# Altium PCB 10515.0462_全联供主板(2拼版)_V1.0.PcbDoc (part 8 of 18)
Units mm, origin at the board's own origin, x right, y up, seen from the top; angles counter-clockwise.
Board outline 282 x 198 mm, 2 copper layers (Top Layer, Bottom Layer); 716 components, 0 nets, 2364 pads, 1800 vias.
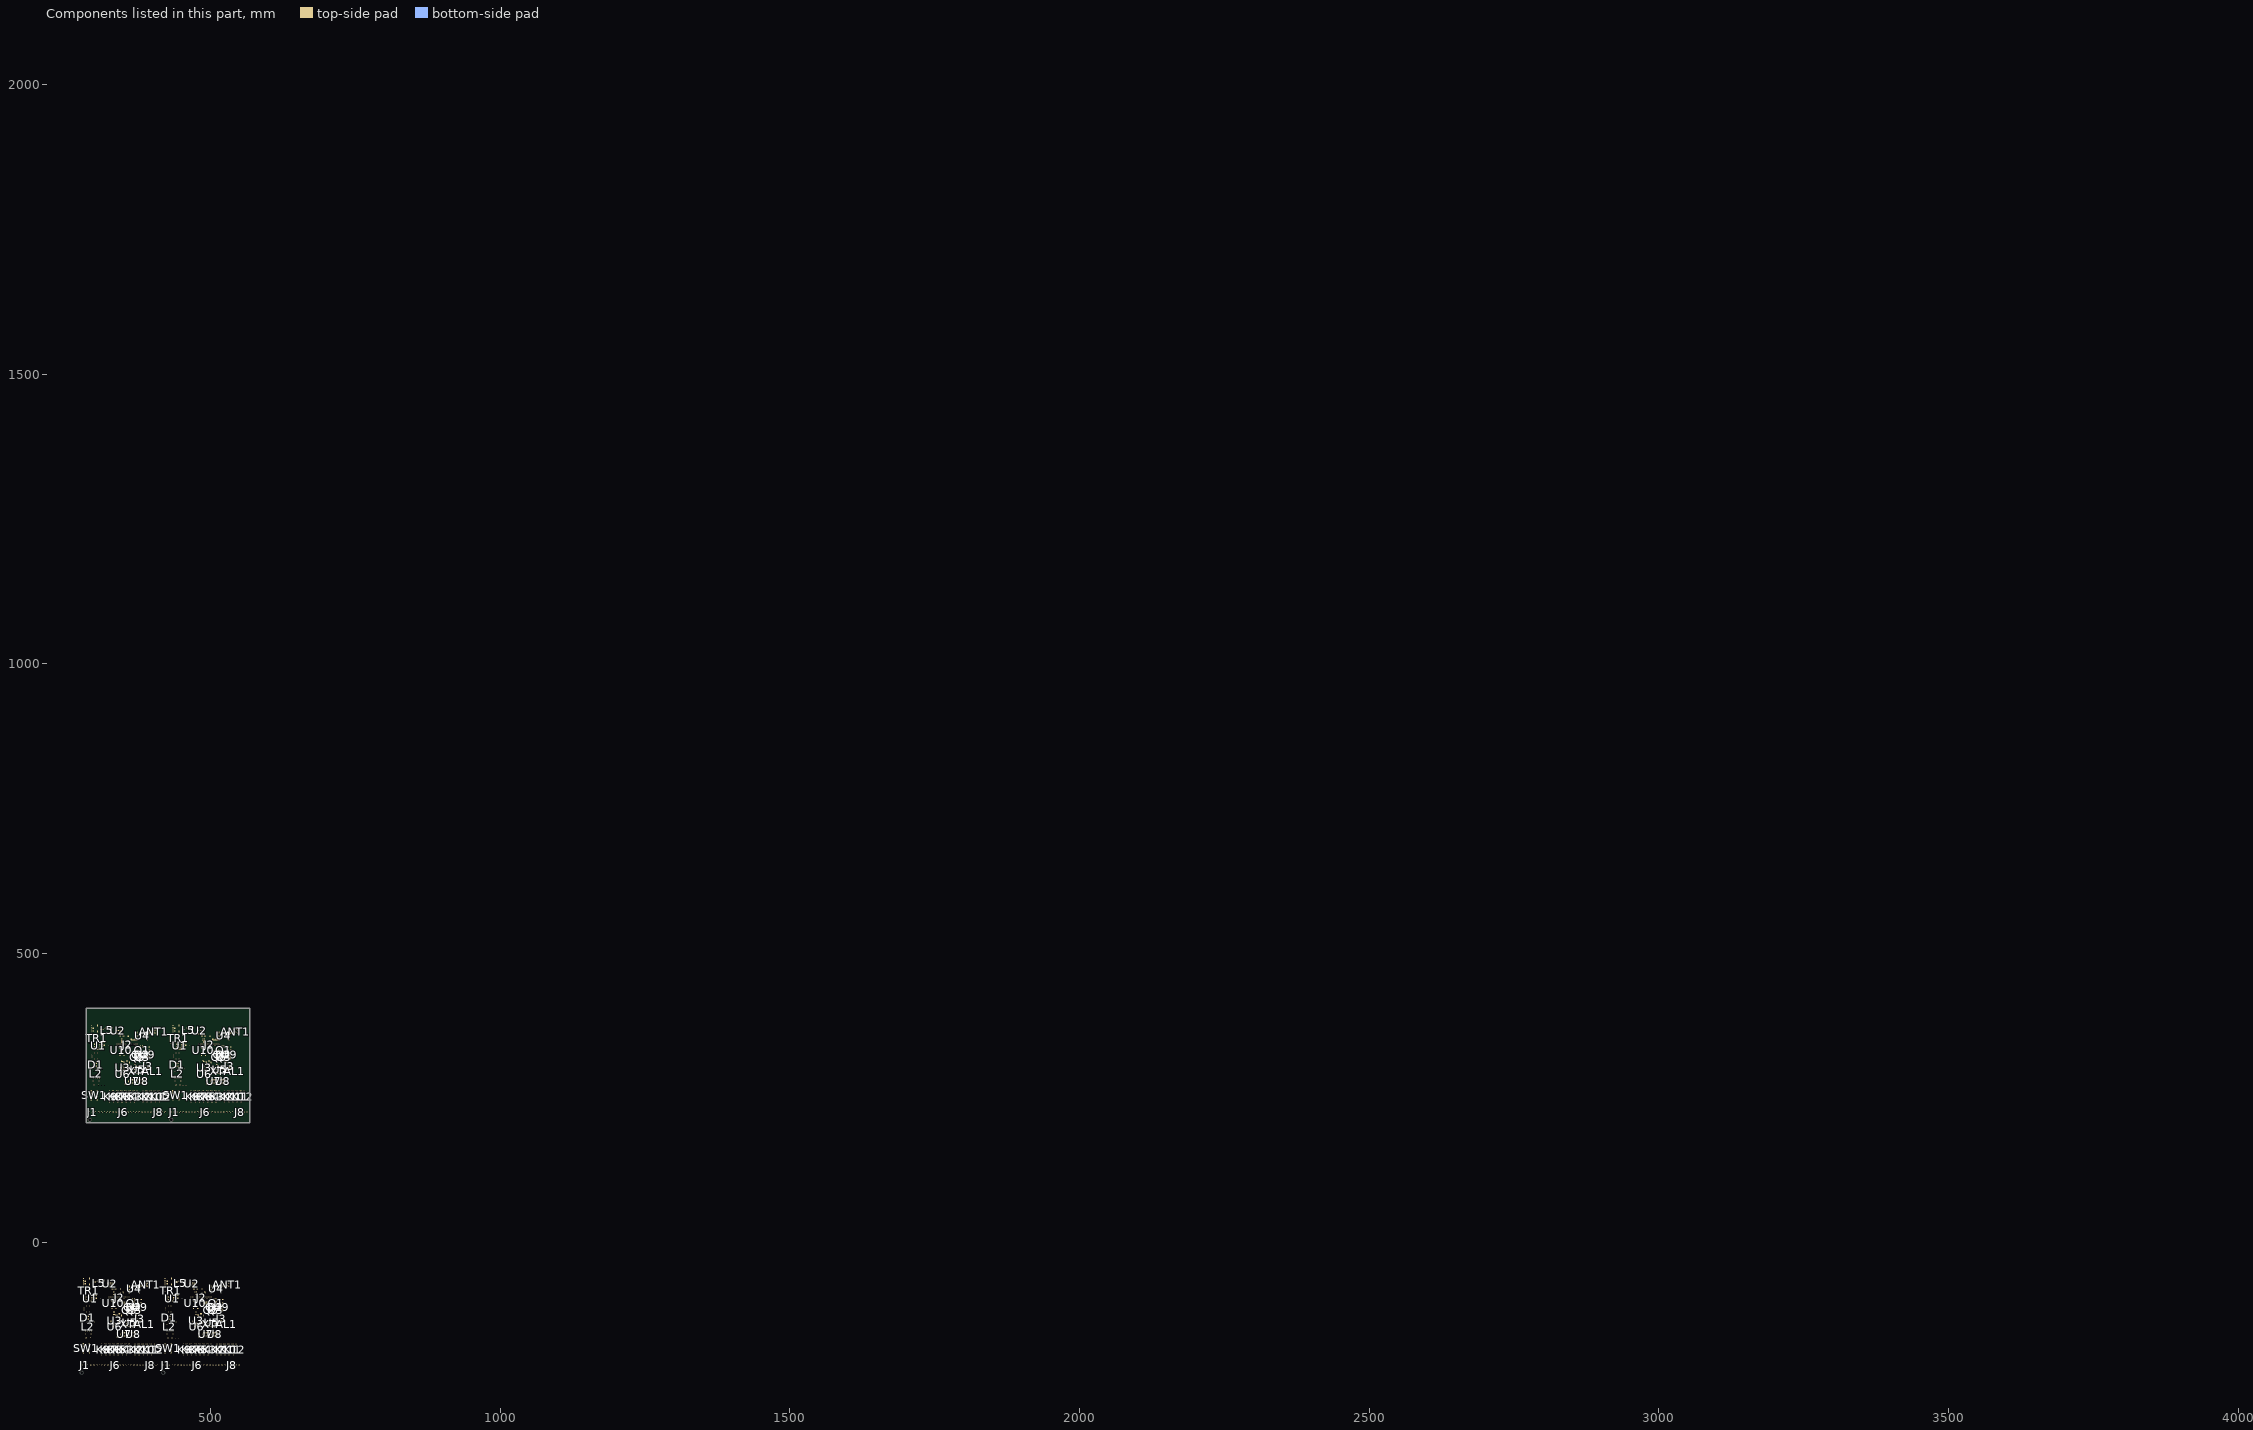
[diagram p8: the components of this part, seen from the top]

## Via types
v1: diameter 0.7, hole 0.4, Top Layer to Bottom Layer, tented both sides, 1800 vias

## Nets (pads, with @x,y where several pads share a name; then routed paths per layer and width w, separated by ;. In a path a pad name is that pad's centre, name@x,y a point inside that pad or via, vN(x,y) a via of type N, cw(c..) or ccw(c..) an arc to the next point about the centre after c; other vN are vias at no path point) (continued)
copper on no net: (continued)
  Top Layer w0.45: 524.977,-73.768 cw(c523.631,-72.858) v1@523.631,-74.482 ; 525.138,-173.772 cw(c526.042,-172.764) 524.687,-172.764 ; 525.228,320.25 cw(c524.918,319.941) 525.356,319.941 cw(c525.794,319.941) 525.484,320.25 ; 525.228,326.817 ccw(c524.918,327.127) 525.356,327.127 ccw(c525.794,327.127) 525.484,326.817 ; 525.349,-74.944 ccw(c524.479,-75.533) 524.479,-74.482 ccw(c524.479,-73.431) 525.349,-74.02 ; 525.917,-74.482 v1@523.631,-74.482 ; 525.991,297.303 527.608,297.303 527.999,297.693 527.999,299.132 528.448,299.582 ; 526.119,297.174 cw(c526.429,296.865) 526.429,297.303 cw(c526.429,297.741) 526.119,297.431 ; 526.512,297.303 ccw(c526.512,299.055) 527.751,297.816 ; 527.297,338.398 ccw(c527.297,340.869) 529.043,339.122 ; 527.742,-72.773 ccw(c525.736,-74.779) 525.736,-71.942 ccw(c525.736,-69.105) 527.742,-71.111 ; 527.751,294.821 cw(c526.786,293.855) 528.151,293.855 ; 527.751,298.066 ccw(c527.154,298.663) 527.999,298.663 ccw(c528.844,298.663) 528.246,298.066 ; 527.999,295.193 528.151,295.041 528.151,293.325 528.151,292.539 528.337,292.352 531.071,292.352 531.452,292.733 531.452,296.963 v1(531.418,296.996) 530.721,297.693 ; 527.999,298.151 cw(c529.842,298.151) 528.539,299.454 ; 527.999,298.973 cw(c528.427,298.973) 528.415,299.401 ; 527.999,299.237 cw(c528.755,299.237) 528.22,299.772 ; 528.023,293.197 cw(c527.713,292.887) 528.151,292.887 cw(c528.589,292.887) 528.279,293.197 ; 528.023,293.454 ccw(c527.713,293.763) 528.151,293.763 ccw(c528.589,293.763) 528.279,293.454 ; 528.06,-72.455 ccw(c526.822,-73.692) 526.822,-71.942 ccw(c526.822,-70.192) 528.06,-71.429 ; 528.074,299.207 ccw(c527.699,299.582) 528.229,299.582 ; v1(528.226,326.19) 529.082,326.19 ; 528.383,338.398 ccw(c528.383,339.782) 529.362,338.804 ; 528.523,338.398 cw(c528.523,337.663) 529.043,338.183 ; 528.751,303.075 ccw(c528.441,303.385) 528.879,303.385 ccw(c529.317,303.385) 529.008,303.075 ; 528.879,302.947 528.879,303.602 529.259,303.981 531.291,303.981 532.144,304.834 532.144,305.31 ; 528.954,326.061 ccw(c528.644,325.752) 528.644,326.19 ccw(c528.644,326.628) 528.954,326.318 ; 529.082,326.317 529.437,325.961 v1(533.513,325.961) v1@533.64,325.961 ; 529.21,326.28 ccw(c529.98,327.049) 529.98,325.961 ; 529.424,332.983 cw(c528.291,331.849) 529.894,331.849 cw(c531.497,331.849) 530.363,332.983 ; 529.443,333.94 ccw(c528.493,334.969) v1(529.894,334.969) ccw(c531.295,334.969) 530.344,333.94 ; 529.674,293.454 ccw(c529.364,293.763) 529.802,293.763 ccw(c530.24,293.763) 529.93,293.454 ; 529.751,298.066 ccw(c529.154,298.663) 529.999,298.663 ccw(c530.844,298.663) 530.246,298.066 ; 529.802,293.325 529.802,294.997 529.999,295.193 ; 529.802,293.749 cw(c531.318,293.749) 530.246,294.821 ; 529.894,331.285 529.894,333.452 v1(529.894,334.969) ; 529.894,331.992 ccw(c531.075,331.992) 530.24,331.157 ; 529.933,297.644 cw(c530.351,297.161) 530.802,297.612 ; 529.958,319.548 ccw(c528.412,321.095) 530.598,321.095 ; 529.989,297.668 cw(c530.133,296.21) 531.169,297.246 ; 529.999,298.993 cw(c530.65,298.993) 530.19,299.454 ; 530.086,319.382 530.598,319.894 530.598,322.246 ; 530.086,319.602 ccw(c530.086,320.132) 530.461,319.757 ; 530.099,299.582 529.999,299.481 529.999,297.693 530.721,297.693 ; 530.227,297.303 cw(c530.668,296.793) 531.145,297.27 ; 530.273,297.476 cw(c530.721,297.123) 530.721,297.693 ; 530.273,297.91 ccw(c530.721,298.264) 530.721,297.693 ; 530.276,319.23 ccw(c529.498,320.008) 530.598,320.008 ; 530.402,301.431 ccw(c530.092,301.741) 530.53,301.741 ccw(c530.968,301.741) 530.659,301.431 ; 530.402,302.819 cw(c530.092,302.509) 530.53,302.509 cw(c530.968,302.509) 530.659,302.819 ; 530.53,302.947 530.53,301.341 532.308,301.341 532.312,301.338 ; 530.598,325.961 530.598,328.342 ; 530.659,301.175 cw(c531.06,300.773) 531.06,301.341 ; 530.744,338.183 cw(c531.265,337.663) 531.265,338.398 ; 530.779,262.851 ccw(c530.1,263.712) 531.197,263.712 ; 530.905,338.861 ccw(c531.545,339.072) 531.545,338.398 ; 531.197,261.97 531.197,263.712 ; 531.322,-173.798 ccw(c530.169,-172.645) 531.799,-172.645 ccw(c533.429,-172.645) 532.276,-173.798 ; v1@531.33,296.908 cw(c531.034,296.613) 531.452,296.613 ; 531.506,319.548 ccw(c530.632,320.423) v1@531.868,320.423 ; 531.592,304.283 ccw(c531.12,304.755) 531.676,305.125 ; 531.615,262.851 cw(c532.294,263.712) 531.197,263.712 ; 531.634,319.382 531.868,319.616 v1(531.868,320.491) 531.868,322.246 ; 531.672,331.157 ccw(c531.363,331.467) 531.801,331.467 ccw(c532.239,331.467) 531.929,331.157 ; 531.709,301.341 cw(c531.709,300.773) 532.111,301.175 ; 531.71,330.901 cw(c531.329,330.52) 531.868,330.52 ; 531.801,331.029 531.801,338.143 531.545,338.398 ; 531.868,328.342 531.868,330.961 ; v1@531.937,320.594 533.138,320.594 533.138,322.246 ; v1@531.957,320.403 cw(c532.419,319.941) 532.419,320.594 ; 532.047,302.632 cw(c531.406,301.992) 532.312,301.992 cw(c533.217,301.992) 532.577,302.632 ; 532.187,301.431 ccw(c531.886,301.732) 532.312,301.732 ; 532.277,301.303 532.312,301.338 ; 532.312,301.75 ccw(c532.762,301.75) 532.444,301.431 ; 532.312,302.838 532.312,301.338 ; 533.005,336.938 ccw(c531.386,338.558) 533.675,338.631 ; 533.183,319.382 534.731,319.382 ; 533.196,331.157 ccw(c532.887,331.467) 533.325,331.467 ccw(c533.763,331.467) 533.453,331.157 ; 533.311,319.254 cw(c533.621,318.944) 533.621,319.382 cw(c533.621,319.82) 533.311,319.51 ; 533.325,331.029 533.325,331.793 532.815,332.302 532.815,336.747 534.72,338.652 ; 533.74,337.673 ccw(c532.809,338.603) 534.125,338.646 ; 533.856,337.788 cw(c534.339,337.305) 534.339,337.988 ; 533.923,339.17 ccw(c533.012,340.303) 534.466,340.303 ; 533.928,301.303 534.318,301.303 535.912,302.897 535.912,305.078 536.144,305.31 ; 533.966,301.484 ccw(c533.966,302.771) 534.876,301.861 ; 534.303,333.969 ccw(c533.597,334.842) v1(534.72,334.842) ccw(c535.843,334.842) 535.137,333.969 ; 534.408,319.44 534.408,322.246 ; 534.408,320.638 ccw(c535.949,320.638) 534.86,319.548 ; 534.408,324.539 v1(534.408,326.841) ; 534.466,339.949 ccw(c535.635,339.949) 534.808,339.122 ; 534.603,319.254 ccw(c534.293,318.944) 534.293,319.382 ccw(c534.293,319.82) 534.603,319.51 ; 534.72,333.452 v1(534.72,334.842) ; 534.885,330.901 cw(c533.445,329.461) 535.482,329.461 ; 534.93,301.915 ccw(c533.949,302.897) 535.337,302.897 ; 534.976,331.029 535.482,330.523 535.482,326.206 v1(535.228,325.952) ; 535.003,330.848 cw(c534.972,330.339) 535.482,330.339 ; v1@535.14,326.041 ccw(c534.313,326.867) 535.482,326.867 ; 535.195,331.029 ccw(c535.725,331.029) 535.35,330.654 ; 535.204,331.219 cw(c534.532,330.547) 535.482,330.547 ; 535.647,303.162 ccw(c535.006,303.802) 535.912,303.802 ccw(c536.817,303.802) 536.177,303.162 ; 535.746,305.039 cw(c535.346,304.639) 535.912,304.639 ; 535.912,303.519 cw(c538.062,303.519) 536.541,305.039 ; 535.912,304.606 cw(c536.975,304.606) 536.223,305.358 ; 536.042,364.82 536.208,364.654 542.201,364.654 ; 536.311,364.538 cw(c536.59,364.259) 536.59,364.654 ; 536.311,364.795 ccw(c536.651,365.135) 536.651,364.654 ; 537.865,262.823 ccw(c536.961,263.832) 538.316,263.832 ; 538.316,261.97 538.316,263.832 ; 538.561,-173.798 ccw(c537.408,-172.645) 539.038,-172.645 ccw(c540.668,-172.645) 539.515,-173.798 ; 538.605,361.399 ccw(c537.26,360.49) v1@537.26,362.114 ; 538.605,362.828 cw(c537.26,363.738) v1@537.26,362.114 ; 538.766,262.823 cw(c539.671,263.832) 538.316,263.832 ; 538.978,361.651 ccw(c538.108,361.063) 538.108,362.114 ccw(c538.108,363.164) 538.978,362.576 ; 539.546,362.114 v1@537.26,362.114 ; 541.371,363.823 ccw(c539.365,361.817) 539.365,364.654 ccw(c539.365,367.49) 541.371,365.484 ; 541.689,364.141 ccw(c540.451,362.903) 540.451,364.654 ccw(c540.451,366.404) 541.689,365.166 ; 544.95,262.798 ccw(c543.798,263.95) 545.428,263.95 ccw(c547.057,263.95) 545.905,262.798 ; 552.189,262.798 ccw(c551.037,263.95) 552.667,263.95 ccw(c554.296,263.95) 553.144,262.798 ; 321.544,-71.781 321.925,-71.781 ; 321.544,-71.781 321.544,-71.219 321.598,-71.273 322.433,-71.273 ; 321.925,-71.781 322.433,-71.273 ; 322.433,-71.273 cw(c322.433,-70.843) 322.012,-70.93 ccw(c322.433,-70.843) 322.433,-71.273 ; 322.433,-71.273 v1@322.814,-71.273 ; 335.173,364.814 335.554,364.814 ; 335.173,364.814 335.173,365.377 335.227,365.322 336.062,365.322 ; 335.554,364.814 336.062,365.322 ; 336.062,365.322 cw(c336.062,365.753) 335.64,365.665 ccw(c336.062,365.753) 336.062,365.322 ; 336.062,365.322 v1@336.443,365.322 ; 345.683,-158.635 346.309,-158.635 ; 345.86,-156.984 346.343,-156.501 346.343,-156.236 ; 345.86,-156.984 344.488,-156.984 344.756,-157.252 359.009,-157.252 ; 345.86,-156.984 359.982,-156.984 ; 346.309,-158.635 359.982,-158.635 360.406,-158.635 ; 355.233,-174.116 354.597,-174.752 355.233,-174.116 ; 355.233,-174.116 355.233,-171.222 ; 359.009,-157.252 361.086,-157.252 361.71,-156.628 ; 359.009,-157.252 359.714,-157.252 359.982,-156.984 ; 359.311,277.96 359.938,277.96 ; 359.489,279.611 359.972,280.094 359.972,280.359 ; 359.489,279.611 358.117,279.611 358.385,279.343 372.638,279.343 ; 359.489,279.611 373.611,279.611 ; 359.938,277.96 373.611,277.96 374.035,277.96 ; 359.982,-156.984 360.787,-156.984 ; 360.113,-158.76 cw(c360.406,-159.04) 360.406,-158.635 ; 360.113,-158.76 cw(c360.406,-159.04) 360.406,-158.635 ; 360.113,-158.76 cw(c360.406,-159.04) 360.406,-158.635 ; 360.113,-158.51 ccw(c360.406,-158.23) 360.406,-158.635 ; 360.113,-158.51 ccw(c360.406,-158.23) 360.406,-158.635 ; 360.113,-158.51 ccw(c360.406,-158.23) 360.406,-158.635 ; 360.42,-158.635 ccw(c360.42,-159.073) 360.11,-158.763 cw(c360.42,-159.073) 360.42,-158.635 ; 360.42,-158.635 cw(c360.42,-158.197) 360.11,-158.507 ccw(c360.42,-158.197) 360.42,-158.635 ; 360.787,-156.984 361.354,-156.984 361.71,-156.628 ; 368.862,262.479 368.226,261.843 368.862,262.479 ; 368.862,262.479 368.862,265.373 ; 372.638,279.343 374.715,279.343 375.339,279.967 ; 372.638,279.343 373.343,279.343 373.611,279.611 ; 373.611,279.611 374.416,279.611 ; 373.742,277.835 cw(c374.035,277.555) 374.035,277.96 ; 373.742,277.835 cw(c374.035,277.555) 374.035,277.96 ; 373.742,277.835 cw(c374.035,277.555) 374.035,277.96 ; 373.742,278.086 ccw(c374.035,278.365) 374.035,277.96 ; 373.742,278.086 ccw(c374.035,278.365) 374.035,277.96 ; 373.742,278.086 ccw(c374.035,278.365) 374.035,277.96 ; 374.049,277.96 ccw(c374.049,277.523) 373.739,277.832 cw(c374.049,277.523) 374.049,277.96 ; 374.049,277.96 cw(c374.049,278.398) 373.739,278.089 ccw(c374.049,278.398) 374.049,277.96 ; 374.416,279.611 374.983,279.611 375.339,279.967 ; 462.544,-71.781 462.925,-71.781 ; 462.544,-71.781 462.544,-71.219 462.598,-71.273 463.433,-71.273 ; 462.925,-71.781 463.433,-71.273 ; 463.433,-71.273 cw(c463.433,-70.843) 463.012,-70.93 ccw(c463.433,-70.843) 463.433,-71.273 ; 463.433,-71.273 v1@463.814,-71.273 ; 476.173,364.814 476.554,364.814 ; 476.173,364.814 476.173,365.377 476.227,365.322 477.062,365.322 ; 476.554,364.814 477.062,365.322 ; 477.062,365.322 cw(c477.062,365.753) 476.64,365.665 ccw(c477.062,365.753) 477.062,365.322 ; 477.062,365.322 v1@477.443,365.322 ; 486.683,-158.635 487.309,-158.635 ; 486.86,-156.984 487.343,-156.501 487.343,-156.236 ; 486.86,-156.984 485.488,-156.984 485.756,-157.252 500.009,-157.252 ; 486.86,-156.984 500.982,-156.984 ; 487.309,-158.635 500.982,-158.635 501.406,-158.635 ; 496.233,-174.116 495.597,-174.752 496.233,-174.116 ; 496.233,-174.116 496.233,-171.222 ; 500.009,-157.252 502.086,-157.252 502.71,-156.628 ; 500.009,-157.252 500.714,-157.252 500.982,-156.984 ; 500.311,277.96 500.938,277.96 ; 500.489,279.611 500.972,280.094 500.972,280.359 ; 500.489,279.611 499.117,279.611 499.385,279.343 513.638,279.343 ; 500.489,279.611 514.611,279.611 ; 500.938,277.96 514.611,277.96 515.035,277.96 ; 500.982,-156.984 501.787,-156.984 ; 501.113,-158.76 cw(c501.406,-159.04) 501.406,-158.635 ; 501.113,-158.76 cw(c501.406,-159.04) 501.406,-158.635 ; 501.113,-158.76 cw(c501.406,-159.04) 501.406,-158.635 ; 501.113,-158.51 ccw(c501.406,-158.23) 501.406,-158.635 ; 501.113,-158.51 ccw(c501.406,-158.23) 501.406,-158.635 ; 501.113,-158.51 ccw(c501.406,-158.23) 501.406,-158.635 ; 501.42,-158.635 ccw(c501.42,-159.073) 501.11,-158.763 cw(c501.42,-159.073) 501.42,-158.635 ; 501.42,-158.635 cw(c501.42,-158.197) 501.11,-158.507 ccw(c501.42,-158.197) 501.42,-158.635 ; 501.787,-156.984 502.354,-156.984 502.71,-156.628 ; 509.862,262.479 509.226,261.843 509.862,262.479 ; 509.862,262.479 509.862,265.373 ; 513.638,279.343 515.715,279.343 516.339,279.967 ; 513.638,279.343 514.343,279.343 514.611,279.611 ; 514.611,279.611 515.416,279.611 ; 514.742,277.835 cw(c515.035,277.555) 515.035,277.96 ; 514.742,277.835 cw(c515.035,277.555) 515.035,277.96 ; 514.742,277.835 cw(c515.035,277.555) 515.035,277.96 ; 514.742,278.086 ccw(c515.035,278.365) 515.035,277.96 ; 514.742,278.086 ccw(c515.035,278.365) 515.035,277.96 ; 514.742,278.086 ccw(c515.035,278.365) 515.035,277.96 ; 515.049,277.96 ccw(c515.049,277.523) 514.739,277.832 cw(c515.049,277.523) 515.049,277.96 ; 515.049,277.96 cw(c515.049,278.398) 514.739,278.089 ccw(c515.049,278.398) 515.049,277.96 ; 515.416,279.611 515.983,279.611 516.339,279.967
  Top Layer w0.5: 330.801,-72.415 330.801,-70.804 332.198,-70.804 ; 344.43,364.181 344.43,365.791 345.827,365.791 ; 369.345,-135.237 ccw(c369.456,-134.63) 369.892,-135.066 ; 369.407,-134.937 370.021,-134.937 370.566,-134.392 v1(370.566,-128.169) ; 369.435,-134.745 ccw(c369.664,-133.49) 370.566,-134.392 ; 382.974,301.359 ccw(c383.085,301.965) 383.521,301.529 ; 383.036,301.659 383.65,301.659 384.195,302.203 v1(384.195,308.426) ; 383.064,301.851 ccw(c383.293,303.105) 384.195,302.203 ; 471.801,-72.415 471.801,-70.804 473.198,-70.804 ; 485.43,364.181 485.43,365.791 486.827,365.791 ; 510.345,-135.237 ccw(c510.456,-134.63) 510.892,-135.066 ; 510.407,-134.937 511.021,-134.937 511.566,-134.392 v1(511.566,-128.169) ; 510.435,-134.745 ccw(c510.664,-133.49) 511.566,-134.392 ; 523.974,301.359 ccw(c524.085,301.965) 524.521,301.529 ; 524.036,301.659 524.65,301.659 525.195,302.203 v1(525.195,308.426) ; 524.064,301.851 ccw(c524.293,303.105) 525.195,302.203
